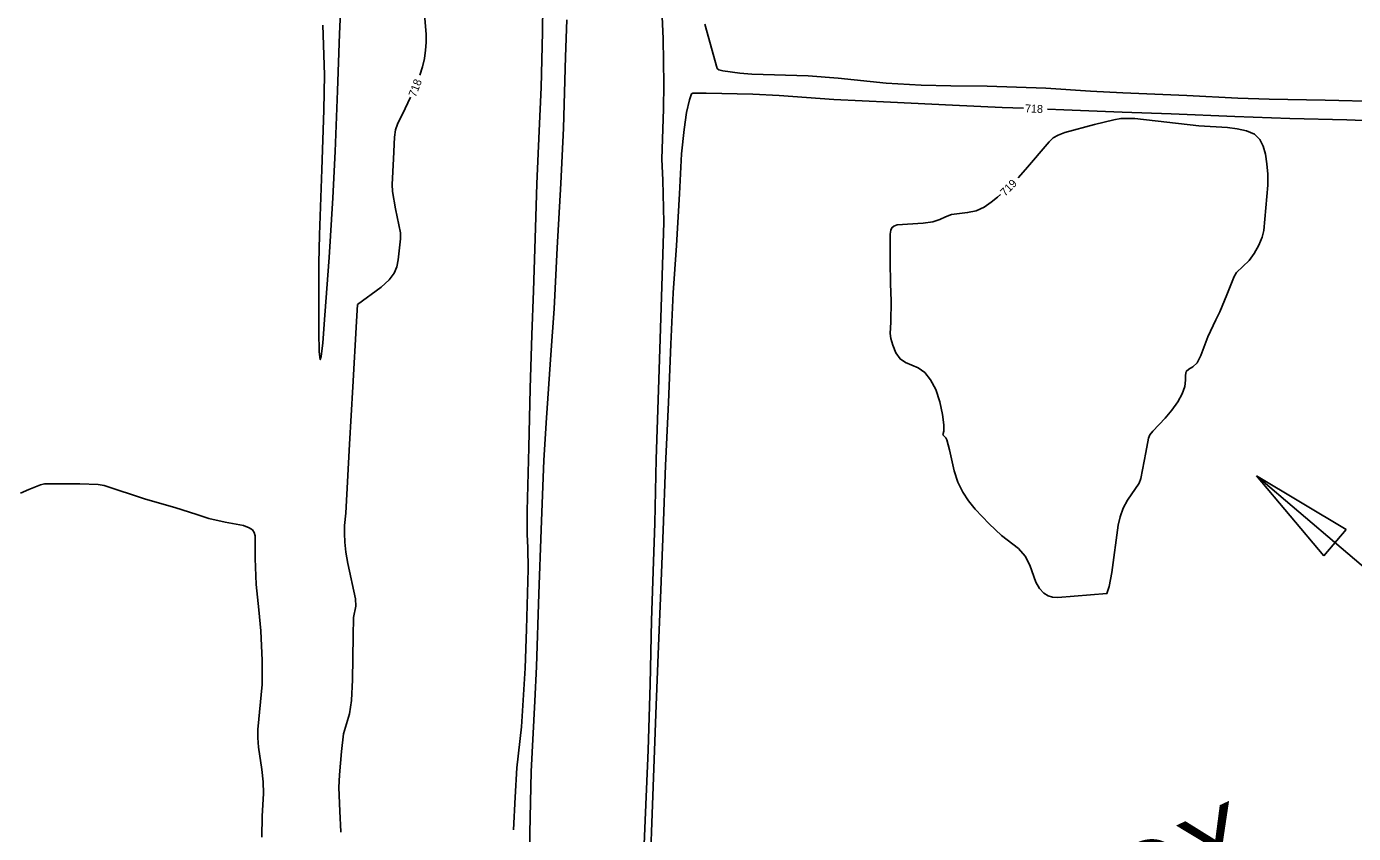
# Model space of a CAD drawing. Extents: x -310467766 to 17062430, y -322263100 to 8322522.
# Drawn here: x 1397464 to 1398127, y 573076 to 573479 of the extents above; entities that cross this region are included whole.
import ezdxf

# ---------------------------------------------------------------- set-up
doc = ezdxf.new("R2010")
doc.units = 0
for name, color, linetype in [('DT_X_Contour_Minor', 7, 'Continuous'), ('Level 19', 7, 'Continuous'), ('Level 40', 7, 'Continuous')]:
    doc.layers.add(name, color=color, linetype=linetype)

msp = doc.modelspace()

# ---------------------------------------------------------------- linework, layer by layer
at = {"layer": 'DT_X_Contour_Minor'}
for points in [[(1397612.49, 573479.81), (1397613.24, 573455.05), (1397612.95, 573437.41), (1397611.96, 573407.68), (1397610.76, 573374.96), (1397610.48, 573360.92), (1397610.37, 573326.53), (1397610.54, 573316.6), (1397611.09, 573312.69), (1397611.53, 573314.15), (1397612.43, 573321.14), (1397613.43, 573334.87), (1397615.56, 573363.75), (1397617.42, 573393.5), (1397618.6, 573416.63), (1397619.72, 573446.94), (1397620.73, 573475.58), (1397621.96, 573500.99)], [(1397772.55, 573058.49), (1397773.69, 573086.33), (1397775.03, 573117.38), (1397776.07, 573150.47), (1397776.72, 573182.2), (1397777.61, 573211.68), (1397778.4, 573230.88), (1397779.05, 573262.89), (1397780.04, 573292.6), (1397780.91, 573323.14), (1397782, 573354.51), (1397782.8, 573381.36), (1397782.32, 573402.43), (1397781.81, 573412.86), (1397782.66, 573437.96), (1397782.83, 573450.35), (1397782.42, 573473.04), (1397781.04, 573506.43)], [(1397707.62, 573077.63), (1397708.5, 573093.97), (1397709.29, 573108.62), (1397711.61, 573129.18), (1397713.52, 573158.42), (1397714.12, 573178.02), (1397715.08, 573207.97), (1397714.91, 573218.75), (1397714.52, 573225.25), (1397714.52, 573237.03), (1397715.28, 573268.72), (1397716.03, 573298.29), (1397716.86, 573325.14), (1397717.7, 573347.07), (1397718.75, 573378.49), (1397719.35, 573400.57), (1397720.52, 573427.06), (1397721.6, 573448.62), (1397722.23, 573476.31), (1397722.38, 573489.92)], [(1397663.34, 573483.4), (1397664.11, 573475.21), (1397664.11, 573471.25)], [(1397734.41, 573482.53), (1397733.61, 573463.94), (1397732.66, 573428.29), (1397731.4, 573400.65), (1397729.55, 573368.58), (1397727.96, 573338.1), (1397726.38, 573315.13), (1397724.17, 573283.63), (1397722.85, 573262.34), (1397721.52, 573227.52), (1397720.34, 573195.52), (1397719.13, 573159.22), (1397718.35, 573141.93), (1397716.58, 573106.83), (1397715.91, 573075.92), (1397715.48, 573047.19)], [(1397803.38, 573480.42), (1397809.49, 573458.2), (1397810.34, 573457.54), (1397812.32, 573457.02), (1397820.87, 573455.86), (1397826.81, 573455.41), (1397854.9, 573454.56), (1397869.95, 573453.39), (1397893.91, 573450.92), (1397911.39, 573449.77), (1397926.24, 573449.44), (1397944.34, 573449.42), (1397973.79, 573448.32), (1397995.99, 573446.92), (1398012.14, 573445.98), (1398044.21, 573444.76), (1398069.6, 573443.36), (1398085.32, 573442.79), (1398113.24, 573442.42), (1398140.46, 573441.73)], [(1397664.11, 573471.25), (1397663.78, 573467.31), (1397663.14, 573463.24), (1397662.16, 573458.94), (1397660.92, 573454.83)], [(1397656.23, 573443.78), (1397653.61, 573438.27), (1397649.71, 573430.37), (1397648.77, 573427.45), (1397648.23, 573423.82), (1397647.65, 573413.01), (1397647.03, 573400.15), (1397647.22, 573396.65), (1397648.73, 573388.07), (1397651.27, 573376.01), (1397651.19, 573373.01), (1397649.99, 573362.58), (1397649.38, 573359.13), (1397648.13, 573355.88), (1397645.62, 573352.53), (1397641.54, 573348.92), (1397629.8, 573340.14), (1397629.3, 573331.74), (1397627.36, 573299.07), (1397625.73, 573270.47), (1397623.83, 573235.93), (1397623.31, 573229.76), (1397623.23, 573225.82), (1397623.43, 573221.39), (1397623.99, 573216.4), (1397624.99, 573210.73), (1397628.77, 573193.05), (1397628.89, 573189.45), (1397627.68, 573183.78), (1397627.63, 573174.37), (1397627.31, 573152.53), (1397626.73, 573142.24), (1397625.77, 573135.6), (1397622.8, 573125.56), (1397621.72, 573116.73), (1397620.71, 573105.1), (1397620.49, 573098.87), (1397620.97, 573086.94), (1397621.39, 573076.67), (1397621.38, 573076.44)], [(1397962.6, 573438.29), (1397951.92, 573438.71), (1397927.08, 573439.86), (1397896.05, 573441.41), (1397867.84, 573442.77), (1397840.39, 573444.77), (1397827.28, 573445.34), (1397803.89, 573445.78), (1397797.27, 573445.92), (1397796.59, 573445.51), (1397795.58, 573442.5), (1397794.2, 573436.18), (1397792.94, 573427.69), (1397791.67, 573415.46), (1397790.59, 573395.55), (1397789.13, 573369.65), (1397787.42, 573346.03), (1397786.31, 573320.38), (1397785.08, 573291.31), (1397783.73, 573259.69), (1397782.49, 573227.49), (1397781.37, 573197.54), (1397780.07, 573169.48), (1397779.01, 573139.88), (1397778.04, 573112.72), (1397776.92, 573085.69), (1397776.15, 573062.92)], [(1398153.5, 573431.43), (1398124.05, 573432.56), (1398095.65, 573433.22), (1398068.12, 573434.27), (1398036.29, 573435.48), (1398011.85, 573436.43), (1397982.65, 573437.5), (1397974.59, 573437.82)], [(1397951.07, 573395.24), (1397949.49, 573393.89), (1397946.36, 573391.33), (1397942.86, 573388.88), (1397938.92, 573387.04), (1397934.6, 573386.13), (1397926.52, 573385.16), (1397923.53, 573384.06), (1397920.69, 573382.69), (1397917.16, 573381.5), (1397912.4, 573380.86), (1397899.49, 573379.99), (1397897.67, 573379.39), (1397896.7, 573378.55), (1397896.19, 573377.4), (1397895.95, 573375.45), (1397895.85, 573361.83), (1397896.15, 573350.63), (1397896.39, 573342.06), (1397896.32, 573331.44), (1397896, 573325.72), (1397896.28, 573323.2), (1397897.18, 573319.82), (1397898.72, 573316.14), (1397900.89, 573313.06), (1397903.62, 573311.18), (1397909.99, 573308.53), (1397913.19, 573306.18), (1397916.15, 573302.63), (1397918.7, 573297.73), (1397920.66, 573291.56), (1397922, 573285.21), (1397922.67, 573280.02), (1397922.71, 573276.96), (1397922.32, 573275.05), (1397923.15, 573274.23), (1397923.77, 573273.6), (1397924.29, 573272.61), (1397925.5, 573267.65), (1397927.92, 573257.14), (1397929.81, 573251.41), (1397932.24, 573246.4), (1397935.14, 573242.03), (1397938.46, 573237.98), (1397945.44, 573230.61), (1397951.5, 573224.8), (1397960.01, 573218.24), (1397963.36, 573214.41), (1397965.66, 573210.01), (1397968.7, 573201.45), (1397970.52, 573198.26), (1397972.63, 573195.98), (1397974.83, 573194.56), (1397977.05, 573193.91), (1397979.67, 573193.83), (1398004.26, 573195.74), (1398005.38, 573199.23), (1398006.63, 573206.21), (1398009.89, 573229.9), (1398010.83, 573234.16), (1398012.35, 573238.42), (1398014.55, 573242.41), (1398020.35, 573250.97), (1398021.12, 573253.23), (1398023.62, 573266.28), (1398024.96, 573273.35), (1398025.7, 573275.05), (1398027.22, 573276.87), (1398033.29, 573283.33), (1398036.74, 573287.41), (1398039.68, 573291.56), (1398041.86, 573295.56), (1398043.12, 573299.22), (1398043.44, 573302.36), (1398043.44, 573304.88), (1398043.86, 573306.67), (1398045.23, 573307.82), (1398047.25, 573309.01), (1398049.38, 573311.12), (1398051.23, 573314.72), (1398054.63, 573324.09), (1398058.69, 573332.5), (1398060.74, 573336.56), (1398064.2, 573345.02), (1398067.76, 573354.23), (1398069.07, 573356.14), (1398075.29, 573362.15), (1398077.82, 573365.71), (1398080.13, 573369.82), (1398081.83, 573373.81), (1398082.65, 573377.21), (1398084.65, 573399.81), (1398084.61, 573405.34), (1398084.16, 573410.57), (1398083.4, 573415.31), (1398082.36, 573419.41), (1398080.7, 573422.77), (1398077.99, 573425.33), (1398074, 573427.06), (1398069.26, 573428.1), (1398064.52, 573428.64)], [(1398064.52, 573428.64), (1398050.18, 573429.45), (1398018.18, 573433.13), (1398013.64, 573433.27), (1398011.2, 573433.11), (1398007.75, 573432.57), (1397998.03, 573430.15), (1397983.22, 573426.13), (1397979.79, 573424.92), (1397977.4, 573423.57), (1397975.3, 573421.55), (1397963.62, 573407.7), (1397959.81, 573403.47)], [(1397581.9, 573074.01), (1397582.1, 573084.48), (1397582.75, 573095.73), (1397582.65, 573101.68), (1397581.99, 573107.76), (1397580.24, 573118.99), (1397579.9, 573123.54), (1397580.01, 573127.79), (1397582.09, 573150.29), (1397582.08, 573162.2), (1397581.41, 573177.12), (1397580.39, 573187.63), (1397579.11, 573200.23), (1397578.62, 573213.29), (1397578.56, 573224.59), (1397578.18, 573226.22), (1397577.3, 573227.54), (1397575.59, 573228.67), (1397572.7, 573229.68), (1397563.65, 573231.48), (1397555.38, 573233.22), (1397549.38, 573235.19), (1397538.46, 573238.83), (1397523.79, 573242.97), (1397503.12, 573249.81), (1397500.17, 573250.28), (1397490.96, 573250.52), (1397473.41, 573250.61), (1397471.27, 573250), (1397465.52, 573247.78), (1397461.38, 573245.98)]]:
    msp.add_lwpolyline(points, dxfattribs=at)
at = {"layer": 'Level 40'}
for p, q in [((1398079.01, 573254.6), (1398215.63, 573138.23)), ((1398112.7, 573214.61), (1398079.01, 573254.6)), ((1398079.01, 573254.6), (1398123.83, 573227.69)), ((1398123.83, 573227.69), (1398112.7, 573214.61))]:
    msp.add_line(p, q, dxfattribs=at)

# ---------------------------------------------------------------- texts
at = {"layer": 'Level 19'}
for s, rotation, p in [('718', 69.0586, (1397658.81, 573443.6)), ('718', 357.74912, (1397963.28, 573436.26)), ('719', 45.14334, (1397953.33, 573394.04))]:
    msp.add_text(s, height=4, rotation=rotation, dxfattribs=at).set_placement(p)
at = {"layer": 'Level 40'}
msp.add_text("EX. 8'X4' BOX", height=37.5, rotation=25, dxfattribs=at).set_placement((1397790.3, 572922.54))

doc.saveas('drawing.dxf')
